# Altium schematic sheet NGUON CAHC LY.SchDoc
size A
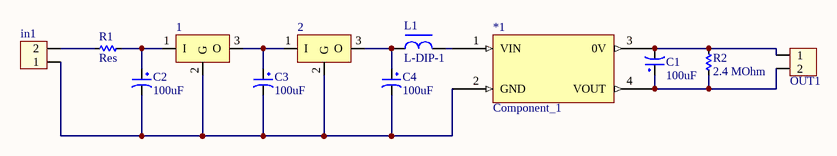
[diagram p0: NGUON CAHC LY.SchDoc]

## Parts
1  LM78xx  [TO220H1]  (value not drawn)
2  LM78xx  [TO220H1]  (value not drawn)
*1  Component_1  [PCBComponent_1]
C1  100uF  [CP1.5/3.4]
C2  100uF  [CP1.5/3.4]
C3  100uF  [CP1.5/3.4]
C4  100uF  [CP1.5/3.4]
in1  12v dc  [HED2]  (value not drawn)
L1  L-DIP-1  [L-DIP-M-9.5x5.5]
OUT1  12v dc  [HED2]  (value not drawn)
R1  Res  [RES-2W]
R2  2.4 MOhm  [RES-1/2W]

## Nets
Net1_1: 1.1(I) C2.1 R1.1
Net1_2: 1.2(G) 2.2(G) *1.2(GND) C2.2 C3.2 C4.2 in1.1
Net1_3: 1.3(O) 2.1(I) C3.1
Net2_3: 2.3(O) C4.1 L1.1
Net*1_1: *1.1(VIN) L1.2
Net*1_3: *1.3(0V) C1.2 OUT1.1 R2.1
Net*1_4: *1.4(VOUT) C1.1 OUT1.2 R2.2
Netin1_2: in1.2 R1.2

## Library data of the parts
1 2 = LM78xx: Positive Voltage Regulator; Note: Tab is connected to pin 3 (GND).
C1-C4 = CP3: Cap 100uF/35V - 470uF/16V; Value: 100uF/35V/50V; Description 1: 1000uF/6,3V - 470uF/16V - 330uF - 25V; Description 2: 220uF/35V - 100uF/50V - 63V - 4,7uF/200V; Description 3: 22uF => 33uF100V - 3,3uF => 4,7uF/250V; Description 4: 2,2uF =>3,3uF/350 - 2,2uF/400V - 1uF/450V
in1 OUT1 = Hed2: Header 2 (Green)
L1 = L-DIP-1: Inductor; Value: 150 mH
R1 R2 = Res: Manufacturer: Generic Components; Class: Passive; SubClass: R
